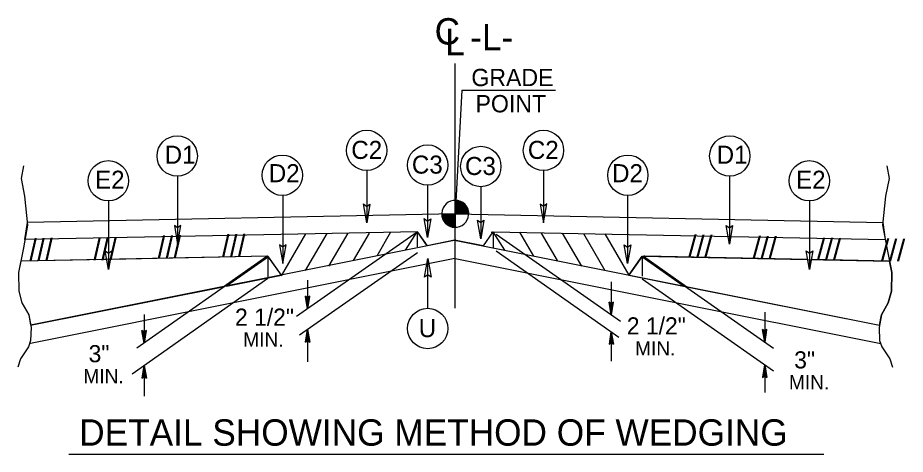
# Model space of a CAD drawing. Extents: x 1901582 to 1902252, y 193723 to 194156.
# Drawn here: x 1902077.02 to 1902110.71, y 194138.34 to 194154.89 of the extents above; entities that cross this region are included whole.
import ezdxf

# ---------------------------------------------------------------- set-up
doc = ezdxf.new("R2010")
doc.units = 0
for name, color, linetype in [('Old_Level_1', 7, 'Continuous'), ('Old_Level_11', 7, 'Continuous'), ('Old_Level_2', 7, 'Continuous'), ('Old_Level_20', 7, 'Continuous'), ('Old_Level_21', 7, 'Continuous'), ('Old_Level_3', 7, 'Continuous')]:
    doc.layers.add(name, color=color, linetype=linetype)

msp = doc.modelspace()

# ---------------------------------------------------------------- linework, layer by layer
at = {"layer": 'Old_Level_1'}
for p, q in [((1902093.623, 194147.452), (1902093.623, 194147.963)), ((1902093.112, 194147.452), (1902093.623, 194147.452)), ((1902093.62, 194146.941), (1902093.62, 194147.446)), ((1902093.623, 194147.452), (1902093.623, 194146.941)), ((1902094.136, 194147.452), (1902093.623, 194147.452)), ((1902093.623, 194146.941), (1902093.623, 194147.452)), ((1902087.937, 194146.689), (1902087.015, 194145.107)), ((1902092.177, 194146.762), (1902087.603, 194143.558)), ((1902088.747, 194146.705), (1902087.931, 194145.303)), ((1902089.55, 194146.721), (1902088.817, 194145.464)), ((1902090.358, 194146.719), (1902089.75, 194145.679)), ((1902091.172, 194146.761), (1902090.643, 194145.853)), ((1902095.18, 194146.687), (1902099.893, 194143.387)), ((1902096.068, 194146.761), (1902096.597, 194145.853)), ((1902096.882, 194146.719), (1902097.49, 194145.679)), ((1902097.69, 194146.721), (1902098.424, 194145.464)), ((1902098.493, 194146.705), (1902099.31, 194145.303)), ((1902099.304, 194146.689), (1902100.212, 194145.131)), ((1902092.188, 194145.979), (1902087.711, 194142.845)), ((1902095.174, 194146.045), (1902099.841, 194142.778)), ((1902086.517, 194145.846), (1902077.133, 194145.658)), ((1902093.614, 194145.76), (1902077.5, 194142.537)), ((1902086.517, 194145.846), (1902081.535, 194142.357)), ((1902087.028, 194145.129), (1902086.517, 194145.846)), ((1902086.517, 194145.846), (1902086.517, 194145.027)), ((1902093.626, 194145.76), (1902109.777, 194142.529)), ((1902100.213, 194145.131), (1902100.722, 194145.846)), ((1902100.722, 194145.846), (1902110.107, 194145.658)), ((1902100.722, 194145.846), (1902100.722, 194145.085)), ((1902100.723, 194145.846), (1902105.713, 194142.352)), ((1902086.513, 194145.002), (1902081.362, 194141.377)), ((1902086.517, 194145.029), (1902084.883, 194144.701)), ((1902088.019, 194144.938), (1902088.019, 194143.85)), ((1902100.212, 194145.131), (1902102.357, 194144.701)), ((1902100.722, 194144.986), (1902105.705, 194141.496)), ((1902084.883, 194144.701), (1902077.506, 194143.226)), ((1902099.549, 194144.876), (1902099.549, 194143.628)), ((1902088.019, 194143.85), (1902087.935, 194144.327)), ((1902088.019, 194144.265), (1902087.935, 194144.327)), ((1902088.019, 194143.85), (1902087.947, 194144.318)), ((1902087.959, 194144.309), (1902088.019, 194143.85)), ((1902088.019, 194143.85), (1902087.971, 194144.301)), ((1902087.983, 194144.292), (1902088.019, 194143.85)), ((1902088.019, 194143.85), (1902087.995, 194144.283)), ((1902088.008, 194144.274), (1902088.019, 194143.85)), ((1902088.019, 194143.85), (1902088.104, 194144.327)), ((1902088.104, 194144.327), (1902088.019, 194144.265)), ((1902088.092, 194144.318), (1902088.019, 194143.85)), ((1902088.019, 194143.85), (1902088.079, 194144.309)), ((1902088.067, 194144.301), (1902088.019, 194143.85)), ((1902088.019, 194143.85), (1902088.055, 194144.292)), ((1902088.043, 194144.283), (1902088.019, 194143.85)), ((1902088.019, 194143.85), (1902088.031, 194144.274)), ((1902088.019, 194144.265), (1902088.019, 194143.85)), ((1902099.549, 194143.628), (1902099.465, 194144.106)), ((1902099.549, 194144.044), (1902099.465, 194144.106)), ((1902099.549, 194143.628), (1902099.477, 194144.097)), ((1902099.489, 194144.088), (1902099.549, 194143.628)), ((1902099.549, 194143.628), (1902099.501, 194144.079)), ((1902099.513, 194144.07), (1902099.549, 194143.628)), ((1902099.549, 194143.628), (1902099.525, 194144.062)), ((1902099.536, 194144.053), (1902099.549, 194143.628)), ((1902099.549, 194143.628), (1902099.633, 194144.106)), ((1902099.633, 194144.106), (1902099.549, 194144.044)), ((1902099.621, 194144.097), (1902099.549, 194143.628)), ((1902099.549, 194143.628), (1902099.609, 194144.088)), ((1902099.597, 194144.079), (1902099.549, 194143.628)), ((1902099.549, 194143.628), (1902099.585, 194144.07)), ((1902099.573, 194144.062), (1902099.549, 194143.628)), ((1902099.549, 194143.628), (1902099.561, 194144.053)), ((1902099.549, 194144.044), (1902099.549, 194143.628)), ((1902081.815, 194143.638), (1902081.815, 194142.553)), ((1902105.375, 194143.717), (1902105.375, 194142.589)), ((1902081.815, 194142.553), (1902081.731, 194143.03)), ((1902081.815, 194142.969), (1902081.731, 194143.03)), ((1902081.815, 194142.553), (1902081.742, 194143.022)), ((1902081.756, 194143.012), (1902081.815, 194142.553)), ((1902081.815, 194142.553), (1902081.768, 194143.004)), ((1902081.78, 194142.995), (1902081.815, 194142.553)), ((1902081.815, 194142.553), (1902081.791, 194142.987)), ((1902081.803, 194142.978), (1902081.815, 194142.553)), ((1902081.815, 194142.553), (1902081.9, 194143.03)), ((1902081.9, 194143.03), (1902081.815, 194142.969)), ((1902081.887, 194143.022), (1902081.815, 194142.553)), ((1902081.815, 194142.553), (1902081.876, 194143.012)), ((1902081.864, 194143.004), (1902081.815, 194142.553)), ((1902081.815, 194142.553), (1902081.851, 194142.995)), ((1902081.84, 194142.987), (1902081.815, 194142.553)), ((1902081.815, 194142.553), (1902081.828, 194142.978)), ((1902081.815, 194142.969), (1902081.815, 194142.553)), ((1902088.019, 194143.06), (1902087.935, 194142.583)), ((1902087.947, 194142.592), (1902088.019, 194143.06)), ((1902088.019, 194143.06), (1902087.959, 194142.6)), ((1902087.971, 194142.61), (1902088.019, 194143.06)), ((1902088.019, 194143.06), (1902087.983, 194142.618)), ((1902087.995, 194142.627), (1902088.019, 194143.06)), ((1902088.019, 194143.06), (1902088.008, 194142.636)), ((1902088.019, 194143.06), (1902088.019, 194141.835)), ((1902088.019, 194143.06), (1902088.104, 194142.583)), ((1902088.019, 194142.645), (1902088.019, 194143.06)), ((1902088.031, 194142.636), (1902088.019, 194143.06)), ((1902088.019, 194143.06), (1902088.043, 194142.627)), ((1902088.055, 194142.618), (1902088.019, 194143.06)), ((1902088.019, 194143.06), (1902088.067, 194142.61)), ((1902088.079, 194142.6), (1902088.019, 194143.06)), ((1902088.019, 194143.06), (1902088.092, 194142.592)), ((1902099.549, 194142.982), (1902099.465, 194142.505)), ((1902099.477, 194142.515), (1902099.549, 194142.982)), ((1902099.549, 194142.982), (1902099.489, 194142.523)), ((1902099.501, 194142.532), (1902099.549, 194142.982)), ((1902099.549, 194142.982), (1902099.513, 194142.541)), ((1902099.525, 194142.549), (1902099.549, 194142.982)), ((1902099.549, 194142.982), (1902099.536, 194142.558)), ((1902099.549, 194142.982), (1902099.549, 194141.866)), ((1902099.549, 194142.982), (1902099.633, 194142.505)), ((1902099.549, 194142.567), (1902099.549, 194142.982)), ((1902099.561, 194142.558), (1902099.549, 194142.982)), ((1902099.549, 194142.982), (1902099.573, 194142.549)), ((1902099.585, 194142.541), (1902099.549, 194142.982)), ((1902099.549, 194142.982), (1902099.597, 194142.532)), ((1902099.609, 194142.523), (1902099.549, 194142.982)), ((1902099.549, 194142.982), (1902099.621, 194142.515)), ((1902105.375, 194142.589), (1902105.291, 194143.066)), ((1902105.375, 194143.004), (1902105.291, 194143.066)), ((1902105.375, 194142.589), (1902105.303, 194143.057)), ((1902105.315, 194143.048), (1902105.375, 194142.589)), ((1902105.375, 194142.589), (1902105.327, 194143.04)), ((1902105.339, 194143.03), (1902105.375, 194142.589)), ((1902105.375, 194142.589), (1902105.351, 194143.022)), ((1902105.363, 194143.012), (1902105.375, 194142.589)), ((1902105.375, 194142.589), (1902105.459, 194143.066)), ((1902105.459, 194143.066), (1902105.375, 194143.004)), ((1902105.447, 194143.057), (1902105.375, 194142.589)), ((1902105.375, 194142.589), (1902105.435, 194143.048)), ((1902105.423, 194143.04), (1902105.375, 194142.589)), ((1902105.375, 194142.589), (1902105.411, 194143.03)), ((1902105.399, 194143.022), (1902105.375, 194142.589)), ((1902105.375, 194142.589), (1902105.387, 194143.012)), ((1902105.375, 194143.004), (1902105.375, 194142.589)), ((1902087.935, 194142.583), (1902088.019, 194142.645)), ((1902088.019, 194142.645), (1902088.104, 194142.583)), ((1902099.465, 194142.505), (1902099.549, 194142.567)), ((1902099.549, 194142.567), (1902099.633, 194142.505)), ((1902081.815, 194141.695), (1902081.731, 194141.217)), ((1902081.744, 194141.226), (1902081.815, 194141.695)), ((1902081.815, 194141.695), (1902081.756, 194141.235)), ((1902081.768, 194141.244), (1902081.815, 194141.695)), ((1902081.815, 194141.695), (1902081.78, 194141.253)), ((1902081.791, 194141.261), (1902081.815, 194141.695)), ((1902081.815, 194141.695), (1902081.803, 194141.27)), ((1902081.815, 194141.695), (1902081.815, 194140.534)), ((1902081.815, 194141.695), (1902081.9, 194141.217)), ((1902081.815, 194141.279), (1902081.815, 194141.695)), ((1902081.828, 194141.27), (1902081.815, 194141.695)), ((1902081.815, 194141.695), (1902081.84, 194141.261)), ((1902081.852, 194141.253), (1902081.815, 194141.695)), ((1902081.815, 194141.695), (1902081.864, 194141.244)), ((1902081.876, 194141.235), (1902081.815, 194141.695)), ((1902081.815, 194141.695), (1902081.887, 194141.226)), ((1902105.375, 194141.728), (1902105.291, 194141.25)), ((1902105.303, 194141.259), (1902105.375, 194141.728)), ((1902105.375, 194141.728), (1902105.315, 194141.268)), ((1902105.327, 194141.277), (1902105.375, 194141.728)), ((1902105.375, 194141.728), (1902105.339, 194141.286)), ((1902105.351, 194141.295), (1902105.375, 194141.728)), ((1902105.375, 194141.728), (1902105.363, 194141.303)), ((1902105.375, 194141.728), (1902105.375, 194140.68)), ((1902105.375, 194141.728), (1902105.459, 194141.25)), ((1902105.375, 194141.313), (1902105.375, 194141.728)), ((1902105.387, 194141.303), (1902105.375, 194141.728)), ((1902105.375, 194141.728), (1902105.399, 194141.295)), ((1902105.411, 194141.286), (1902105.375, 194141.728)), ((1902105.375, 194141.728), (1902105.423, 194141.277)), ((1902105.435, 194141.268), (1902105.375, 194141.728)), ((1902105.375, 194141.728), (1902105.447, 194141.259)), ((1902081.731, 194141.217), (1902081.815, 194141.279)), ((1902081.815, 194141.279), (1902081.9, 194141.217)), ((1902105.291, 194141.25), (1902105.375, 194141.313)), ((1902105.375, 194141.313), (1902105.459, 194141.25))]:
    msp.add_line(p, q, dxfattribs=at)
for points in [[(1902077.233, 194149.271), (1902077.147, 194148.795), (1902077.277, 194148.119), (1902077.391, 194147.025), (1902077.233, 194146.16), (1902077.046, 194145.224), (1902077.061, 194144.518), (1902077.176, 194144.072), (1902077.436, 194143.625), (1902077.522, 194143.136), (1902077.507, 194142.646), (1902077.421, 194142.415), (1902077.119, 194141.955), (1902077.018, 194141.638)], [(1902110.007, 194149.271), (1902110.093, 194148.795), (1902109.964, 194148.119), (1902109.849, 194147.025), (1902110.007, 194146.16), (1902110.194, 194145.224), (1902110.18, 194144.518), (1902110.064, 194144.072), (1902109.805, 194143.625), (1902109.719, 194143.136), (1902109.733, 194142.646), (1902109.82, 194142.415), (1902110.122, 194141.955), (1902110.222, 194141.638)], [(1902093.628, 194147.963), (1902093.628, 194147.963), (1902093.628, 194147.452)], [(1902093.638, 194147.963), (1902093.638, 194147.452)], [(1902093.649, 194147.963), (1902093.649, 194147.452)], [(1902093.659, 194147.963), (1902093.659, 194147.452)], [(1902093.67, 194147.962), (1902093.67, 194147.452)], [(1902093.679, 194147.96), (1902093.679, 194147.452)], [(1902093.69, 194147.96), (1902093.69, 194147.452)], [(1902093.7, 194147.958), (1902093.7, 194147.452)], [(1902093.71, 194147.956), (1902093.71, 194147.452)], [(1902093.72, 194147.954), (1902093.72, 194147.452)], [(1902093.731, 194147.953), (1902093.731, 194147.452)], [(1902093.742, 194147.95), (1902093.742, 194147.452)], [(1902093.752, 194147.948), (1902093.751, 194147.452)], [(1902093.762, 194147.945), (1902093.762, 194147.452)], [(1902093.771, 194147.942), (1902093.771, 194147.452)], [(1902093.781, 194147.939), (1902093.781, 194147.452)], [(1902093.792, 194147.935), (1902093.792, 194147.452)], [(1902093.803, 194147.932), (1902093.803, 194147.452)], [(1902093.813, 194147.927), (1902093.813, 194147.452)], [(1902093.823, 194147.923), (1902093.823, 194147.452)], [(1902093.833, 194147.919), (1902093.833, 194147.452)], [(1902093.843, 194147.914), (1902093.843, 194147.452)], [(1902093.853, 194147.909), (1902093.853, 194147.452)], [(1902093.864, 194147.904), (1902093.864, 194147.452)], [(1902093.874, 194147.898), (1902093.874, 194147.452)], [(1902093.885, 194147.892), (1902093.885, 194147.452)], [(1902093.895, 194147.886), (1902093.894, 194147.452)], [(1902093.905, 194147.88), (1902093.905, 194147.452)], [(1902093.915, 194147.873), (1902093.915, 194147.452)], [(1902093.925, 194147.865), (1902093.925, 194147.452)], [(1902093.936, 194147.858), (1902093.936, 194147.452)], [(1902093.946, 194147.85), (1902093.946, 194147.452)], [(1902093.956, 194147.841), (1902093.956, 194147.452)], [(1902093.966, 194147.832), (1902093.966, 194147.452)], [(1902093.977, 194147.822), (1902093.977, 194147.452)], [(1902093.986, 194147.813), (1902093.986, 194147.452)], [(1902093.997, 194147.802), (1902093.997, 194147.452)], [(1902094.007, 194147.79), (1902094.007, 194147.452)], [(1902094.017, 194147.778), (1902094.017, 194147.452)], [(1902094.028, 194147.766), (1902094.028, 194147.452)], [(1902094.038, 194147.753), (1902094.037, 194147.452)], [(1902094.048, 194147.738), (1902094.048, 194147.452)], [(1902094.058, 194147.722), (1902094.058, 194147.452)], [(1902094.068, 194147.705), (1902094.068, 194147.452)], [(1902094.079, 194147.686), (1902094.079, 194147.452)], [(1902094.089, 194147.664), (1902094.089, 194147.452)], [(1902094.099, 194147.641), (1902094.099, 194147.452)], [(1902094.109, 194147.612), (1902094.109, 194147.452)], [(1902093.115, 194147.452), (1902093.115, 194147.396)], [(1902093.125, 194147.452), (1902093.125, 194147.337)], [(1902093.136, 194147.452), (1902093.136, 194147.3)], [(1902093.146, 194147.452), (1902093.146, 194147.27)], [(1902093.155, 194147.452), (1902093.155, 194147.244)], [(1902093.166, 194147.452), (1902093.166, 194147.223)], [(1902093.176, 194147.452), (1902093.176, 194147.204)], [(1902093.187, 194147.452), (1902093.187, 194147.186)], [(1902093.197, 194147.452), (1902093.197, 194147.17)], [(1902093.207, 194147.452), (1902093.207, 194147.155)], [(1902093.218, 194147.452), (1902093.218, 194147.141)], [(1902093.227, 194147.452), (1902093.227, 194147.128)], [(1902093.237, 194147.452), (1902093.237, 194147.116)], [(1902093.247, 194147.452), (1902093.247, 194147.105)], [(1902093.258, 194147.452), (1902093.258, 194147.094)], [(1902093.268, 194147.452), (1902093.268, 194147.085)], [(1902093.279, 194147.452), (1902093.279, 194147.074)], [(1902093.289, 194147.452), (1902093.289, 194147.065)], [(1902093.299, 194147.452), (1902093.299, 194147.056)], [(1902093.309, 194147.452), (1902093.309, 194147.049)], [(1902093.319, 194147.452), (1902093.319, 194147.041)], [(1902093.33, 194147.452), (1902093.33, 194147.034)], [(1902093.34, 194147.452), (1902093.34, 194147.026)], [(1902093.351, 194147.452), (1902093.351, 194147.02)], [(1902093.361, 194147.452), (1902093.36, 194147.013)], [(1902093.37, 194147.452), (1902093.37, 194147.007)], [(1902093.38, 194147.452), (1902093.38, 194147.002)], [(1902093.391, 194147.452), (1902093.391, 194146.996)], [(1902093.401, 194147.452), (1902093.401, 194146.991)], [(1902093.412, 194147.452), (1902093.412, 194146.987)], [(1902093.422, 194147.452), (1902093.422, 194146.982)], [(1902093.432, 194147.452), (1902093.432, 194146.978)], [(1902093.442, 194147.452), (1902093.442, 194146.974)], [(1902093.453, 194147.452), (1902093.453, 194146.97)], [(1902093.462, 194147.452), (1902093.462, 194146.967)], [(1902093.473, 194147.452), (1902093.473, 194146.964)], [(1902093.483, 194147.452), (1902093.483, 194146.961)], [(1902093.494, 194147.452), (1902093.494, 194146.958)], [(1902093.504, 194147.452), (1902093.503, 194146.955)], [(1902093.513, 194147.452), (1902093.513, 194146.953)], [(1902093.524, 194147.452), (1902093.524, 194146.951)], [(1902093.534, 194147.452), (1902093.534, 194146.949)], [(1902093.545, 194147.452), (1902093.545, 194146.947)], [(1902093.555, 194147.452), (1902093.555, 194146.945)], [(1902093.566, 194147.452), (1902093.566, 194146.945)], [(1902093.575, 194147.452), (1902093.575, 194146.943)], [(1902093.585, 194147.452), (1902093.585, 194146.942)], [(1902093.596, 194147.452), (1902093.595, 194146.941)], [(1902093.606, 194147.452), (1902093.606, 194146.941)], [(1902093.616, 194147.452), (1902093.616, 194146.941), (1902093.616, 194146.941)], [(1902094.12, 194147.577), (1902094.12, 194147.452)], [(1902094.129, 194147.525), (1902094.129, 194147.452)]]:
    msp.add_lwpolyline(points, dxfattribs=at)
for start, end in [(358.0003, 356.1713), (359.9905, 89.9905), (179.9905, 268.7186), (269.6533, 269.9905)]:
    msp.add_arc((1902093.623, 194147.452), 0.512, start, end, dxfattribs=at)
at = {"layer": 'Old_Level_11'}
for p, q in [((1902093.62, 194143.872), (1902093.62, 194153.155)), ((1902090.264, 194149.092), (1902090.264, 194147.114)), ((1902096.976, 194149.092), (1902096.976, 194147.114)), ((1902083.085, 194148.88), (1902083.085, 194146.298)), ((1902104.033, 194148.88), (1902104.033, 194146.298)), ((1902092.577, 194148.535), (1902092.577, 194146.557)), ((1902094.595, 194148.482), (1902094.595, 194146.504)), ((1902080.465, 194147.938), (1902080.465, 194145.343)), ((1902087.077, 194148.15), (1902087.077, 194145.569)), ((1902100.163, 194148.15), (1902100.163, 194145.569)), ((1902107.074, 194147.938), (1902107.074, 194145.343)), ((1902093.62, 194147.452), (1902077.384, 194147.128)), ((1902093.62, 194147.452), (1902109.856, 194147.128)), ((1902093.621, 194147.452), (1902109.856, 194147.128)), ((1902077.292, 194146.476), (1902077.384, 194147.128)), ((1902109.856, 194147.128), (1902109.95, 194146.476)), ((1902092.196, 194146.774), (1902077.292, 194146.476)), ((1902091.734, 194146.08), (1902092.175, 194146.768)), ((1902092.175, 194146.768), (1902092.175, 194146.202)), ((1902092.56, 194146.239), (1902092.196, 194146.774)), ((1902092.196, 194146.756), (1902092.56, 194146.239)), ((1902095.056, 194146.774), (1902094.68, 194146.239)), ((1902094.993, 194146.753), (1902095.015, 194146.752)), ((1902095.033, 194146.762), (1902095.056, 194146.761)), ((1902095.056, 194146.774), (1902109.95, 194146.476)), ((1902095.506, 194146.08), (1902095.066, 194146.768)), ((1902095.066, 194146.768), (1902095.066, 194146.144)), ((1902093.644, 194146.455), (1902077.506, 194143.226)), ((1902093.596, 194146.455), (1902092.56, 194146.239)), ((1902093.596, 194146.455), (1902109.735, 194143.226)), ((1902094.68, 194146.239), (1902093.596, 194146.455)), ((1902077.133, 194145.658), (1902077.046, 194145.224)), ((1902080.397, 194145.724), (1902077.133, 194145.658)), ((1902086.472, 194145.845), (1902081.72, 194145.75)), ((1902084.819, 194144.688), (1902086.472, 194145.845)), ((1902092.581, 194143.87), (1902092.581, 194145.763)), ((1902100.825, 194145.845), (1902100.768, 194145.845)), ((1902100.768, 194145.845), (1902102.418, 194144.69)), ((1902107.007, 194145.72), (1902100.825, 194145.845)), ((1902110.107, 194145.658), (1902107.139, 194145.717)), ((1902077.506, 194143.226), (1902084.819, 194144.688)), ((1902102.418, 194144.69), (1902102.418, 194144.69)), ((1902102.418, 194144.69), (1902102.418, 194144.69)), ((1902102.418, 194144.69), (1902102.418, 194144.69)), ((1902102.418, 194144.69), (1902102.418, 194144.69)), ((1902102.418, 194144.69), (1902102.418, 194144.69)), ((1902102.418, 194144.69), (1902102.418, 194144.69)), ((1902102.418, 194144.69), (1902109.735, 194143.226)), ((1902109.735, 194143.226), (1902109.805, 194143.625)), ((1902109.735, 194143.226), (1902109.735, 194143.226)), ((1902078.951, 194138.336), (1902107.62, 194138.336))]:
    msp.add_line(p, q, dxfattribs=at)
for points in [[(1902090.386, 194147.823), (1902090.264, 194147.114), (1902090.138, 194147.827), (1902090.264, 194147.736)], [(1902096.853, 194147.823), (1902096.976, 194147.114), (1902097.102, 194147.827), (1902096.976, 194147.736)], [(1902092.7, 194147.266), (1902092.577, 194146.557), (1902092.451, 194147.27), (1902092.577, 194147.179)], [(1902082.963, 194147.007), (1902083.085, 194146.298), (1902083.211, 194147.011), (1902083.085, 194146.92)], [(1902094.717, 194147.212), (1902094.595, 194146.504), (1902094.469, 194147.216), (1902094.595, 194147.126)], [(1902104.155, 194147.007), (1902104.033, 194146.298), (1902103.907, 194147.011), (1902104.033, 194146.92)], [(1902086.955, 194146.278), (1902087.077, 194145.569), (1902087.203, 194146.281), (1902087.077, 194146.191)], [(1902100.285, 194146.278), (1902100.163, 194145.569), (1902100.037, 194146.281), (1902100.163, 194146.191)], [(1902080.587, 194146.052), (1902080.465, 194145.343), (1902080.339, 194146.055), (1902080.465, 194145.965)], [(1902107.196, 194146.052), (1902107.074, 194145.343), (1902106.948, 194146.055), (1902107.074, 194145.965)], [(1902087.028, 194145.129), (1902086.532, 194145.825), (1902084.945, 194144.714)], [(1902092.459, 194145.054), (1902092.581, 194145.763), (1902092.707, 194145.051), (1902092.581, 194145.141)], [(1902100.708, 194145.826), (1902100.213, 194145.131), (1902102.295, 194144.714)]]:
    msp.add_lwpolyline(points, close=True, dxfattribs=at)
for points in [[(1902081.72, 194145.75), (1902080.531, 194145.726), (1902080.465, 194145.343), (1902080.397, 194145.724)], [(1902107.139, 194145.717), (1902107.074, 194145.343), (1902107.007, 194145.72)], [(1902109.805, 194143.625), (1902110.064, 194144.072), (1902110.18, 194144.518), (1902110.194, 194145.224), (1902110.107, 194145.658)], [(1902077.046, 194145.224), (1902077.061, 194144.518), (1902077.176, 194144.072)], [(1902077.176, 194144.072), (1902077.436, 194143.625), (1902077.506, 194143.226)]]:
    msp.add_lwpolyline(points, dxfattribs=at)
for centre in [(1902083.071, 194149.645), (1902090.264, 194149.857), (1902096.975, 194149.857), (1902104.047, 194149.645), (1902092.577, 194149.301), (1902094.595, 194149.247), (1902087.062, 194148.915), (1902100.177, 194148.915), (1902080.457, 194148.704), (1902107.067, 194148.704), (1902092.581, 194143.104)]:
    msp.add_circle(centre, 0.765, dxfattribs=at)
at = {"layer": 'Old_Level_3'}
for q in [(1902093.621, 194147.452), (1902097.428, 194152.136)]:
    msp.add_line((1902093.871, 194152.136), q, dxfattribs=at)

# ---------------------------------------------------------------- texts
at = {"layer": 'Old_Level_1'}
for height, rotation, p in [(0.8139, 1.1445, (1902082.329, 194145.77)), (0.8139, 1.1463, (1902084.77, 194145.82)), (0.8139, 358.8553, (1902102.471, 194145.82)), (0.8139, 358.8536, (1902104.912, 194145.77)), (0.8142, 1.1447, (1902077.457, 194145.67)), (0.8142, 1.1464, (1902079.89, 194145.699)), (0.8142, 358.8554, (1902107.35, 194145.699)), (0.8142, 358.8537, (1902109.784, 194145.67))]:
    msp.add_text('/// ', height=height, rotation=rotation, dxfattribs=at).set_placement(p)
at = {"layer": 'Old_Level_11'}
for s, p in [('GRADE', (1902094.237, 194152.294)), ('POINT', (1902094.395, 194151.3))]:
    msp.add_text(s, height=0.656, dxfattribs=at).set_placement(p)
at = {"layer": 'Old_Level_2'}
msp.add_text('C', height=1, dxfattribs=at).set_placement((1902092.843, 194153.872))
for s, p in [('L', (1902093.245, 194153.468)), ('-L-', (1902094.194, 194153.65))]:
    msp.add_text(s, height=1, rotation=359.9469, dxfattribs=at).set_placement(p)
at = {"layer": 'Old_Level_20'}
for s, height, p in [('D1', 0.6851, (1902082.595, 194149.351)), ('C2', 0.6851, (1902089.679, 194149.534)), ('C2', 0.6851, (1902096.382, 194149.534)), ('D1', 0.6851, (1902103.55, 194149.351)), ('C3', 0.6851, (1902091.98, 194148.977)), ('C3', 0.6851, (1902093.997, 194148.924)), ('D2', 0.6851, (1902086.548, 194148.651)), ('D2', 0.6851, (1902099.58, 194148.651)), ('E2', 0.6851, (1902079.953, 194148.402)), ('E2', 0.6851, (1902106.563, 194148.402)), ('2 1/2"', 0.6491, (1902085.266, 194143.21)), ('2 1/2"', 0.6491, (1902100.14, 194142.879)), ('U', 0.685, (1902092.239, 194142.775)), ('3"', 0.6491, (1902079.708, 194141.825)), ('3"', 0.6491, (1902106.493, 194141.59))]:
    msp.add_text(s, height=height, dxfattribs=at).set_placement(p)
at = {"layer": 'Old_Level_21'}
for s, height, p in [('MIN.', 0.5424, (1902085.578, 194142.412)), ('MIN.', 0.5424, (1902100.451, 194142.081)), ('MIN.', 0.5424, (1902079.509, 194141.027)), ('MIN.', 0.5424, (1902106.294, 194140.792)), ('DETAIL SHOWING METHOD OF WEDGING', 1, (1902079.351, 194138.66))]:
    msp.add_text(s, height=height, dxfattribs=at).set_placement(p)

doc.saveas('drawing.dxf')
